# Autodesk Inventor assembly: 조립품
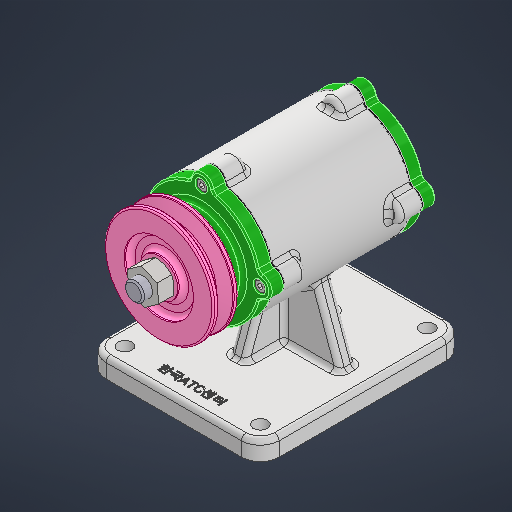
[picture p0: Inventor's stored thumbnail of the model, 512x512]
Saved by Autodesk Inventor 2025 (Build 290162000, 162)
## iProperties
Created: 2025-08
Part Number: 조립품
Document SubType Name: Assembly
Designer: infra17
Author: infra17
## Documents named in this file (12)
- C:\Users\infra17\Desktop\750806V1008\조립품.iam
- C:\Users\infra17\Desktop\750806V1008\본체.ipt
- C:\Users\infra17\Desktop\750806V1008\V-벨트풀리\V-벨트풀리.ipt
- C:\Users\infra17\Desktop\750806V1008\개스킷\개스킷.ipt
- C:\Users\infra17\Desktop\750806V1008\너트 M12 x 1.25\너트 M12 x 1.25.ipt
- C:\Users\infra17\Desktop\750806V1008\뒤커버\뒤커버.ipt
- C:\Users\infra17\Desktop\750806V1008\베어링 6204\베어링 6204.ipt
- C:\Users\infra17\Desktop\750806V1008\볼트 M4 x 12\볼트 M4 x 12.ipt
- C:\Users\infra17\Desktop\750806V1008\앞커버\앞커버.ipt
- C:\Users\infra17\Desktop\750806V1008\오일 실\오일 실.ipt
- C:\Users\infra17\Desktop\750806V1008\축\축.ipt
- C:\Users\infra17\Desktop\750806V1008\키 4 x 4\키 4 x 4.ipt
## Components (3 placed, 2 different names)
1. V-벨트풀리:1
2. 개스킷:1
3. 개스킷:2
